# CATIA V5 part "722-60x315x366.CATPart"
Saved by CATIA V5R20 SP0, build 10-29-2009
Part number: 722-60x315x366
Definition: NONE
Nomenclature: 722-60x315x366
Source: Unknown
Description: 722-60x315x366
Bounding box of the stored display mesh (mm): x -30 to 30, y -30 to 30, z -297 to 69
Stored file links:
  C:\Users\Utente\Desktop\IO LAVORO\3D X SITO CF\X SITO\722\722-60x315x366.CATPart
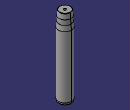
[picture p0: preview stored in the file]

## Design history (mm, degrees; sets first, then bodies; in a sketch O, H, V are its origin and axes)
Body1 "722-60x315x366" (main body)
  Solid1: solid without history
